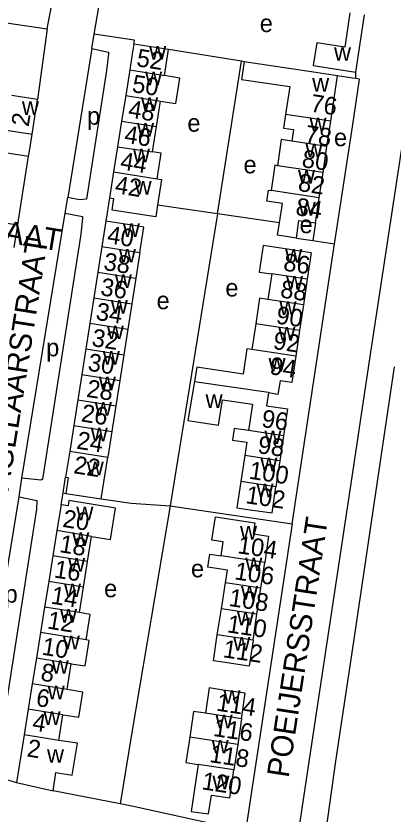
# Model space of a CAD drawing. Extents: x 163012 to 165277, y 382513 to 383987.
# Drawn here: x 163273.7 to 163359.2, y 383043.1 to 383224 of the extents above; entities that cross this region are included whole.
import ezdxf

# ---------------------------------------------------------------- set-up
doc = ezdxf.new("R2010")
doc.units = 0
for name, color, linetype in [('BLT_Basislijn', 7, 'Continuous'), ('BLT_Bebouwing', 7, 'Continuous'), ('BLT_Centroide', 7, 'Continuous'), ('BLT_Huisnummer', 7, 'Continuous'), ('BLT_Huisnummer_ tussenligend', 7, 'Continuous'), ('BLT_Onderverdeling_panden', 7, 'Continuous'), ('BLT_Straatnaam', 7, 'Continuous')]:
    doc.layers.add(name, color=color, linetype=linetype)

msp = doc.modelspace()

# ---------------------------------------------------------------- linework, layer by layer
at = {"layer": 'BLT_Basislijn'}
for p, q in [((163280.84, 383221.02), (163283.14, 383233.7)), ((163291.43, 383219.86), (163293.58, 383232.33)), ((163251.88, 383225.34), (163280.84, 383221.02)), ((163280.84, 383221.02), (163278.64, 383205.01)), ((163290.91, 383216.57), (163291.43, 383219.86)), ((163290.91, 383216.57), (163285.48, 383182.8)), ((163324.86, 383213.74), (163308.33, 383216.34)), ((163319.42, 383179.09), (163324.86, 383213.74)), ((163325.44, 383213.56), (163324.86, 383213.74)), ((163350, 383209.9), (163346.62, 383210.38)), ((163350.74, 383209.8), (163350.75, 383211.22)), ((163350.74, 383209.8), (163350, 383209.9)), ((163276.79, 383193.36), (163277.38, 383197.15)), ((163274.32, 383177.67), (163276.6, 383192.22)), ((163276.6, 383192.22), (163276.79, 383193.36)), ((163284.93, 383179.31), (163285.48, 383182.8)), ((163294.93, 383182.73), (163294.11, 383177.49)), ((163275.1, 383119.24), (163284.93, 383179.31)), ((163319.42, 383179.09), (163305.84, 383181.06)), ((163274.14, 383176.53), (163274.32, 383177.67)), ((163333.46, 383177.05), (163319.42, 383179.09)), ((163273.34, 383171.46), (163274.14, 383176.53)), ((163341.63, 383177.05), (163341.06, 383173.07)), ((163336.35, 383108.85), (163345.97, 383172.34)), ((163337.29, 383173.64), (163341.06, 383173.07)), ((163341.06, 383173.07), (163345.97, 383172.34)), ((163353.87, 383146.27), (163350, 383120.49)), ((163359.45, 383144.46), (163350, 383080.74)), ((163350, 383120.49), (163340.61, 383057.98)), ((163274.43, 383115.01), (163275.1, 383119.24)), ((163284.41, 383115.91), (163285, 383119.49)), ((163283.96, 383113.18), (163284.41, 383115.91)), ((163308.69, 383112.99), (163336.35, 383108.85)), ((163350, 383080.74), (163346.19, 383055.07)), ((163340.61, 383057.98), (163334.42, 383017.07)), ((163346.19, 383055.07), (163341.87, 383024.69)), ((163268.91, 383051.72), (163273.84, 383050.25)), ((163297.38, 383045.46), (163282.15, 383048.4))]:
    msp.add_line(p, q, dxfattribs=at)
for points in [[(163368.47, 383237.95), (163367.9, 383237.24), (163367.52, 383236.23), (163353.87, 383146.27)], [(163300.45, 383217.58), (163300.6, 383218.45), (163300.02, 383218.53), (163291.43, 383219.86)], [(163290.91, 383216.57), (163294.69, 383215.73), (163294.69, 383215.42), (163294.24, 383211.58), (163289.75, 383182.43), (163288.16, 383182.31), (163285.48, 383182.8)], [(163350, 383198.85), (163351.64, 383209.67), (163350.74, 383209.8)], [(163345.97, 383172.34), (163346.19, 383173.75), (163350, 383198.85)], [(163274.14, 383176.53), (163247.15, 383180.75), (163249.57, 383196.36), (163276.6, 383192.22)], [(163284.93, 383179.31), (163288.8, 383178.49), (163288.8, 383178.14), (163288.43, 383174.55), (163279.76, 383119), (163279.44, 383118.81), (163275.1, 383119.24)], [(163319.42, 383179.09), (163319.21, 383177.78), (163308.69, 383112.99)], [(163268.91, 383051.72), (163264.55, 383052.76), (163264.29, 383052.99), (163274.43, 383115.01)], [(163274.43, 383115.01), (163278.49, 383114.17), (163278.4, 383112.22), (163268.91, 383051.72)], [(163284.41, 383115.91), (163285.04, 383115.79)], [(163293.06, 383114.51), (163299.86, 383113.59), (163308.69, 383112.99)], [(163308.69, 383112.99), (163300.01, 383061.58), (163297.38, 383045.46)], [(163336.35, 383108.85), (163325.76, 383039.25)], [(163325.76, 383039.25), (163300.01, 383044.87), (163297.38, 383045.46)]]:
    msp.add_lwpolyline(points, dxfattribs=at)
at = {"layer": 'BLT_Bebouwing'}
for p, q in [((163350.75, 383211.22), (163352.7, 383224.19)), ((163307.39, 383210.44), (163308.33, 383216.34)), ((163299.53, 383211.77), (163298.61, 383205.96)), ((163345.79, 383204.83), (163346.62, 383210.38)), ((163277.38, 383197.15), (163278.64, 383205.01)), ((163298.61, 383205.96), (163297.69, 383200.15)), ((163305.57, 383198.93), (163306.48, 383204.68)), ((163345.08, 383200.1), (163345.79, 383204.83)), ((163297.69, 383200.15), (163296.77, 383194.34)), ((163344.23, 383194.39), (163345.08, 383200.1)), ((163271.57, 383198.08), (163277.38, 383197.15)), ((163304.65, 383193.17), (163305.57, 383198.93)), ((163296.77, 383194.34), (163295.87, 383188.64)), ((163343.34, 383188.48), (163344.23, 383194.39)), ((163295.87, 383188.64), (163294.93, 383182.73)), ((163342.49, 383182.77), (163343.34, 383188.48)), ((163305.75, 383187.09), (163306.76, 383186.93)), ((163306.76, 383186.93), (163305.84, 383181.06)), ((163294.93, 383182.73), (163295.92, 383182.58)), ((163295.51, 383179.96), (163295.92, 383182.58)), ((163341.63, 383177.05), (163342.49, 383182.77)), ((163305.43, 383178.41), (163295.51, 383179.96)), ((163305.84, 383181.06), (163305.43, 383178.41)), ((163294.11, 383177.49), (163293.2, 383171.7)), ((163293.2, 383171.7), (163292.29, 383165.91)), ((163301.83, 383170.34), (163300.92, 383164.55)), ((163340.65, 383170.27), (163339.76, 383164.31)), ((163292.29, 383165.91), (163291.38, 383160.12)), ((163331.73, 383165.51), (163330.86, 383159.74)), ((163300.92, 383164.55), (163300.01, 383158.76)), ((163339.76, 383164.31), (163338.9, 383158.53)), ((163291.38, 383160.12), (163290.47, 383154.33)), ((163300.01, 383158.76), (163299.1, 383152.97)), ((163338.9, 383158.53), (163338.02, 383152.66)), ((163290.47, 383154.33), (163289.56, 383148.53)), ((163328.07, 383154.22), (163327.2, 383148.37)), ((163299.1, 383152.97), (163298.19, 383147.18)), ((163338.02, 383152.66), (163337.15, 383146.88)), ((163289.56, 383148.53), (163288.65, 383142.74)), ((163298.19, 383147.18), (163297.28, 383141.39)), ((163288.65, 383142.74), (163287.74, 383136.95)), ((163297.28, 383141.39), (163296.37, 383135.6)), ((163287.74, 383136.95), (163286.83, 383131.16)), ((163327.34, 383135.96), (163326.45, 383130.01)), ((163296.37, 383135.6), (163295.46, 383129.81)), ((163286.83, 383131.16), (163285.93, 383125.37)), ((163295.46, 383129.81), (163294.55, 383124.02)), ((163334.4, 383128.82), (163333.55, 383123.19)), ((163285.93, 383125.37), (163285, 383119.49)), ((163325.6, 383124.38), (163324.71, 383118.46)), ((163333.55, 383123.19), (163332.66, 383117.27)), ((163283.96, 383113.18), (163283.03, 383107.39)), ((163283.03, 383107.39), (163282.1, 383101.6)), ((163289.96, 383100.33), (163290.87, 383106.04)), ((163282.1, 383101.6), (163281.17, 383095.8)), ((163289.03, 383094.54), (163289.96, 383100.33)), ((163329.24, 383094.3), (163330.11, 383100.13)), ((163281.17, 383095.8), (163280.24, 383090.02)), ((163288.11, 383088.75), (163289.03, 383094.54)), ((163320.33, 383089.62), (163321.21, 383095.5)), ((163328.36, 383088.42), (163329.24, 383094.3)), ((163280.24, 383090.02), (163279.3, 383084.22)), ((163319.38, 383083.72), (163320.33, 383089.62)), ((163327.47, 383082.51), (163328.36, 383088.42)), ((163279.3, 383084.22), (163278.37, 383078.43)), ((163278.37, 383078.43), (163277.44, 383072.64)), ((163285.32, 383071.37), (163286.25, 383077.17)), ((163277.44, 383072.64), (163276.51, 383066.85)), ((163276.51, 383066.85), (163275.58, 383061.06)), ((163283.47, 383059.79), (163284.4, 383065.58)), ((163324.87, 383064.71), (163324, 383058.9)), ((163324, 383058.9), (163323.15, 383053.14)), ((163273.84, 383050.25), (163282.15, 383048.4))]:
    msp.add_line(p, q, dxfattribs=at)
for points in [[(163349.42, 383224.69), (163348.28, 383216.92), (163341.9, 383217.89), (163341.09, 383212.77), (163350.75, 383211.22)], [(163300.45, 383217.58), (163300.02, 383214.85), (163299.53, 383211.77)], [(163308.33, 383216.34), (163305.39, 383216.8), (163300.45, 383217.58)], [(163325.44, 383213.56), (163324.85, 383209.6), (163335.8, 383207.96), (163334.85, 383201.61)], [(163346.62, 383210.38), (163341.68, 383211.12), (163325.44, 383213.56)], [(163306.48, 383204.68), (163309.98, 383204.13), (163310.88, 383209.89), (163307.39, 383210.44)], [(163278.64, 383205.01), (163273.7, 383205.8), (163272.82, 383205.93)], [(163334.85, 383201.61), (163334.39, 383198.54), (163336.67, 383198.2), (163336.28, 383195.58)], [(163336.28, 383195.58), (163333.87, 383195.94), (163332.98, 383190.04)], [(163305.75, 383187.09), (163306.66, 383192.85), (163304.65, 383193.17)], [(163332.98, 383190.04), (163332.42, 383190.12), (163331.56, 383184.39)], [(163333.46, 383177.05), (163334.12, 383181.45), (163330.62, 383181.97), (163331, 383184.47), (163331.56, 383184.39)], [(163301.83, 383170.34), (163302.74, 383176.14), (163300.02, 383176.56), (163294.11, 383177.49)], [(163337.29, 383173.64), (163337.89, 383177.61), (163341.63, 383177.05)], [(163337.29, 383173.64), (163333.04, 383174.27), (163333.46, 383177.05)], [(163340.65, 383170.27), (163335.71, 383171.01), (163329.77, 383171.93), (163328.86, 383165.94), (163331.73, 383165.51)], [(163330.86, 383159.74), (163328.94, 383159.99), (163328.07, 383154.22)], [(163327.2, 383148.37), (163326.1, 383148.53), (163325.25, 383142.83)], [(163337.15, 383146.88), (163336.26, 383140.93), (163333.6, 383141.32), (163333.13, 383138.22), (163330.97, 383138.55)], [(163325.25, 383142.83), (163314.73, 383144.41), (163314.24, 383141.12)], [(163314.24, 383141.12), (163312.68, 383132.31), (163319.66, 383131.26), (163320.52, 383136.99), (163327.34, 383135.96)], [(163330.97, 383138.55), (163330.53, 383135.64), (163335.31, 383134.92), (163334.4, 383128.82)], [(163326.45, 383130.01), (163323.23, 383130.49), (163322.83, 383127.87), (163326.05, 383127.39), (163325.6, 383124.38)], [(163293.06, 383114.51), (163294.55, 383124.02)], [(163285, 383119.49), (163285.6, 383119.37), (163285.04, 383115.79)], [(163324.71, 383118.46), (163323.83, 383112.53), (163326.83, 383112.08), (163331.78, 383111.34), (163332.66, 383117.27)], [(163285.04, 383115.79), (163293.06, 383114.51)], [(163290.87, 383106.04), (163295.19, 383105.35), (163296.33, 383112.46), (163285.74, 383114.17), (163285.54, 383112.92), (163283.96, 383113.18)], [(163320.26, 383101.61), (163320.73, 383104.77), (163318.13, 383105.16), (163318.93, 383110.48), (163327.89, 383109.13), (163327.51, 383106.61), (163331, 383106.08), (163330.11, 383100.13)], [(163321.21, 383095.5), (163321.65, 383098.4), (163317.22, 383099.04), (163317.66, 383101.99), (163320.26, 383101.61)], [(163289.66, 383082.56), (163290.59, 383088.33), (163288.11, 383088.75)], [(163327.47, 383082.51), (163326.59, 383076.61), (163321.64, 383077.35), (163318.51, 383077.87), (163319.38, 383083.72)], [(163286.25, 383077.17), (163289.4, 383076.68), (163290.33, 383082.45), (163289.66, 383082.56)], [(163284.4, 383065.58), (163288.01, 383065.09), (163288.92, 383070.77), (163285.32, 383071.37)], [(163324.87, 383064.71), (163325.72, 383070.47), (163320.71, 383071.19), (163317.53, 383071.69), (163316.67, 383065.94)], [(163316.67, 383065.94), (163314.01, 383066.34), (163313.13, 383060.53)], [(163275.58, 383061.06), (163273.84, 383050.25)], [(163313.13, 383060.53), (163312.27, 383054.77), (163315.03, 383054.36)], [(163282.15, 383048.4), (163282.81, 383052.53), (163286.51, 383051.93), (163287.68, 383059.2), (163283.47, 383059.79)], [(163315.03, 383054.36), (163313.44, 383043.72), (163317.41, 383043.13), (163318.05, 383047.38), (163322.19, 383046.76), (163323.15, 383053.14)]]:
    msp.add_lwpolyline(points, dxfattribs=at)
at = {"layer": 'BLT_Onderverdeling_panden'}
for p, q in [((163299.53, 383211.77), (163307.39, 383210.44)), ((163298.61, 383205.96), (163306.48, 383204.68)), ((163345.08, 383200.1), (163334.85, 383201.61)), ((163297.69, 383200.15), (163305.57, 383198.93)), ((163344.23, 383194.39), (163336.28, 383195.58)), ((163296.77, 383194.34), (163304.65, 383193.17)), ((163295.87, 383188.64), (163305.75, 383187.09)), ((163343.34, 383188.48), (163332.98, 383190.04)), ((163342.49, 383182.77), (163331.56, 383184.39)), ((163293.2, 383171.7), (163301.83, 383170.34)), ((163292.29, 383165.91), (163300.92, 383164.55)), ((163339.76, 383164.31), (163331.73, 383165.51)), ((163291.38, 383160.12), (163300.01, 383158.76)), ((163338.9, 383158.53), (163330.86, 383159.74)), ((163290.47, 383154.33), (163299.1, 383152.97)), ((163338.02, 383152.66), (163328.07, 383154.22)), ((163289.56, 383148.53), (163298.19, 383147.18)), ((163337.15, 383146.88), (163327.2, 383148.37)), ((163288.65, 383142.74), (163297.28, 383141.39)), ((163287.74, 383136.95), (163296.37, 383135.6)), ((163286.83, 383131.16), (163295.46, 383129.81)), ((163334.4, 383128.82), (163326.45, 383130.01)), ((163285.93, 383125.37), (163294.55, 383124.02)), ((163333.55, 383123.19), (163325.6, 383124.38)), ((163332.66, 383117.27), (163324.71, 383118.46)), ((163290.87, 383106.04), (163283.03, 383107.39)), ((163289.96, 383100.33), (163282.1, 383101.6)), ((163330.11, 383100.13), (163320.26, 383101.61)), ((163289.03, 383094.54), (163281.17, 383095.8)), ((163329.24, 383094.3), (163321.21, 383095.5)), ((163288.11, 383088.75), (163280.24, 383090.02)), ((163328.36, 383088.42), (163320.33, 383089.62)), ((163289.66, 383082.56), (163279.3, 383084.22)), ((163327.47, 383082.51), (163319.38, 383083.72)), ((163286.25, 383077.17), (163278.37, 383078.43)), ((163285.32, 383071.37), (163277.44, 383072.64)), ((163284.4, 383065.58), (163276.51, 383066.85)), ((163324.87, 383064.71), (163316.67, 383065.94)), ((163283.47, 383059.79), (163275.58, 383061.06)), ((163324, 383058.9), (163313.13, 383060.53)), ((163323.15, 383053.14), (163315.03, 383054.36))]:
    msp.add_line(p, q, dxfattribs=at)
msp.add_lwpolyline([(163314.24, 383141.12), (163330.99, 383138.69), (163330.97, 383138.55)], dxfattribs=at)

# ---------------------------------------------------------------- texts
at = {"layer": 'BLT_Centroide'}
for s, p in [('e', (163329, 383220.31)), ('w', (163303.93, 383214.06)), ('w', (163345.82, 383213.8)), ('w', (163303.01, 383208.25)), ('w', (163340.87, 383206.84)), ('w', (163275.09, 383201.53)), ('w', (163302.09, 383202.44)), ('p', (163289.85, 383199.32)), ('w', (163301.17, 383196.62)), ('e', (163312.59, 383197.74)), ('w', (163340.27, 383197.84)), ('e', (163345.82, 383194.45)), ('w', (163300.25, 383190.81)), ('w', (163339.37, 383191.94)), ('e', (163325.31, 383188.3)), ('w', (163337.67, 383185.97)), ('w', (163300.63, 383183.47)), ('w', (163337.8, 383178.72)), ('e', (163338.02, 383174.75)), ('w', (163297.97, 383173.91)), ('w', (163297.06, 383168.12)), ('w', (163334.75, 383168.06)), ('w', (163296.15, 383162.34)), ('w', (163334.95, 383161.97)), ('e', (163321.2, 383160.38)), ('w', (163295.23, 383156.53)), ('e', (163305.61, 383157.51)), ('w', (163333.46, 383156.19)), ('w', (163294.33, 383150.75)), ('w', (163333.2, 383150.38)), ('p', (163280.59, 383146.84)), ('w', (163293.42, 383144.97)), ('w', (163330.98, 383143.38)), ('w', (163292.52, 383139.16)), ('w', (163316.71, 383135.12)), ('w', (163291.6, 383133.38)), ('w', (163290.69, 383127.59)), ('w', (163330.05, 383126.94)), ('w', (163329.13, 383120.81)), ('w', (163289.78, 383119.89)), ('w', (163328.25, 383114.91)), ('w', (163287.42, 383109.66)), ('w', (163286.5, 383103.88)), ('w', (163324.52, 383105.31)), ('w', (163285.56, 383098.06)), ('e', (163313.41, 383096.76)), ('w', (163325.71, 383098.16)), ('w', (163284.63, 383092.28)), ('e', (163293.72, 383092.24)), ('w', (163324.74, 383091.72)), ('p', (163271.16, 383091.01)), ('w', (163283.71, 383086.5)), ('w', (163323.84, 383085.88)), ('w', (163284.35, 383080.44)), ('w', (163322.98, 383080.16)), ('w', (163281.84, 383074.91)), ('w', (163280.92, 383069.12)), ('w', (163320.77, 383068.09)), ('w', (163279.98, 383063.31)), ('w', (163318.97, 383062.53)), ('w', (163318.09, 383056.84)), ('w', (163280.77, 383054.72)), ('w', (163318.27, 383048.75))]:
    msp.add_text(s, height=4, dxfattribs=at).set_placement(p)
at = {"layer": 'BLT_Huisnummer'}
for s, rotation, p in [('52', 351.0592, (163300.9, 383212.61)), ('76', 351.4734, (163340.31, 383202.32)), ('2', 80.9151, (163276.6, 383198.73)), ('78', 351.4791, (163339.07, 383195.31)), ('46', 351.002, (163298.14, 383195.26)), ('42', 351.132, (163296.01, 383183.83)), ('84', 351.4699, (163336.97, 383178.86)), ('40', 351.0807, (163294.24, 383172.49)), ('86', 351.4743, (163334.18, 383166.3)), ('34', 351.0813, (163291.69, 383155.13)), ('90', 351.4769, (163332.54, 383154.29)), ('30', 351.0813, (163289.85, 383143.62)), ('94', 351.4818, (163331.07, 383142.81)), ('26', 351.0802, (163288.34, 383132.11)), ('96', 351.4738, (163329.24, 383130.85)), ('22', 351.084, (163286.64, 383120.37)), ('102', 351.476, (163325.64, 383113.58)), ('20', 350.8594, (163284.15, 383108.22)), ('104', 351.4745, (163323.82, 383102.24)), ('14', 350.8615, (163281.51, 383090.83)), ('108', 351.4748, (163321.84, 383090.29)), ('10', 350.8607, (163279.45, 383079.26)), ('112', 351.476, (163320.5, 383078.67)), ('6', 350.8664, (163278.12, 383067.66)), ('114', 351.474, (163319, 383066.57)), ('2', 350.8568, (163276.06, 383056.2)), ('120', 351.4745, (163315.71, 383048.74))]:
    msp.add_text(s, height=4, rotation=rotation, dxfattribs=at).set_placement(p)
at = {"layer": 'BLT_Huisnummer_ tussenligend'}
for s, rotation, p in [('50', 351.002, (163299.88, 383206.74)), ('48', 351.002, (163299.02, 383201)), ('44', 351.132, (163297.21, 383189.23)), ('80', 351.4791, (163338.37, 383189.75)), ('82', 351.4791, (163337.51, 383184.35)), ('38', 351.0813, (163293.43, 383166.44)), ('36', 351.0813, (163292.73, 383160.7)), ('88', 351.4743, (163333.49, 383160.21)), ('32', 351.0813, (163290.74, 383149.19)), ('92', 351.4769, (163331.86, 383148.54)), ('28', 351.0802, (163289.56, 383137.68)), ('24', 351.084, (163287.32, 383125.94)), ('98', 351.4738, (163328.38, 383124.93)), ('100', 351.4738, (163326.4, 383119.13)), ('18', 350.8615, (163283.43, 383102.49)), ('16', 350.8615, (163282.21, 383096.75)), ('106', 351.4745, (163323.12, 383096.32)), ('12', 350.8607, (163280.68, 383085.18)), ('110', 351.4748, (163321.42, 383084.33)), ('8', 350.8664, (163279.17, 383073.4)), ('4', 350.8568, (163277.26, 383062.12)), ('116', 351.474, (163318.3, 383060.83)), ('118', 351.474, (163317.44, 383054.91))]:
    msp.add_text(s, height=4, rotation=rotation, dxfattribs=at).set_placement(p)
at = {"layer": 'BLT_Straatnaam'}
for s, rotation, p in [('SIMON DE VLIEGERSTRAAT', 350.7093, (163194.55, 383185.18)), ('BAGELAARSTRAAT', 81.0469, (163271.33, 383111.85)), ('POEIJERSSTRAAT', 81.3522, (163335.53, 383051.18))]:
    msp.add_text(s, height=5, rotation=rotation, dxfattribs=at).set_placement(p)

doc.saveas('drawing.dxf')
